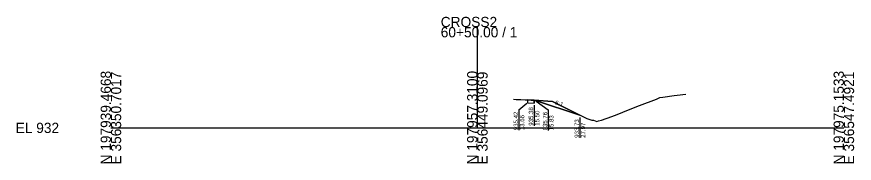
# Model space of a CAD drawing. Extents: x -26 to 203, y -10 to 14021.
# Drawn here: x -25.7 to 202.8, y 1490.3 to 1530.4 of the extents above; entities that cross this region are included whole.
import ezdxf

# ---------------------------------------------------------------- set-up
doc = ezdxf.new("R2010")
doc.units = 0
for name, color, linetype in [('Default', 7, 'Continuous'), ('P_E_XS_Ground', 7, 'Continuous'), ('P_XS', 7, 'Continuous'), ('P_XS_EAR_CommonGrnd', 7, 'Continuous'), ('P_XS_Lane', 7, 'Continuous'), ('P_XS_Rock', 7, 'Continuous')]:
    doc.layers.add(name, color=color, linetype=linetype)

msp = doc.modelspace()

# ---------------------------------------------------------------- linework, layer by layer
at = {"layer": 'Default'}
for p, q in [((100, 1500), (100, 1527.59)), ((0, 1500), (100, 1500)), ((100, 1500), (200, 1500))]:
    msp.add_line(p, q, dxfattribs=at)
at = {"layer": 'P_E_XS_Ground'}
for p, q in [((149.82, 1508.3), (150.61, 1508.37)), ((150.61, 1508.37), (153.73, 1508.85)), ((153.73, 1508.85), (154.52, 1508.94)), ((154.52, 1508.94), (156.89, 1509.2)), ((109.83, 1507.83), (110.55, 1507.8)), ((110.55, 1507.8), (115.5, 1507.6)), ((115.5, 1507.6), (120.5, 1507.2)), ((120.5, 1507.2), (129.85, 1502.53)), ((141.22, 1504.91), (144.22, 1506.13)), ((144.22, 1506.13), (148.91, 1507.86)), ((148.91, 1507.86), (149.82, 1508.3)), ((138.16, 1503.69), (141.22, 1504.91)), ((129.85, 1502.53), (131.24, 1502.11)), ((131.24, 1502.11), (131.69, 1502.12)), ((131.69, 1502.12), (132.62, 1501.78)), ((132.62, 1501.78), (133.06, 1501.93)), ((133.06, 1501.93), (133.85, 1502.13)), ((133.85, 1502.13), (136.69, 1503.12)), ((136.69, 1503.12), (138.16, 1503.69))]:
    msp.add_line(p, q, dxfattribs=at)
at = {"layer": 'P_XS'}
for p, q in [((109.83, 1507.83), (113.83, 1507.67)), ((113.83, 1507.67), (115.5, 1507.54))]:
    msp.add_line(p, q, dxfattribs=at)
at = {"layer": 'P_XS_EAR_CommonGrnd'}
msp.add_lwpolyline([(113.66, 1507.67), (113.66, 1506.84), (115.5, 1506.77), (115.5, 1507.54), (115.83, 1507.51), (127.97, 1503.46), (120.5, 1507.2), (115.5, 1507.6)], close=True, dxfattribs=at)
at = {"layer": 'P_XS_Lane'}
for p, q in [((113.66, 1507.67), (113.66, 1506.84)), ((113.66, 1506.84), (115.5, 1506.77)), ((115.5, 1507.54), (115.5, 1506.77)), ((115.5, 1507.54), (115.83, 1507.51)), ((127.97, 1503.46), (115.83, 1507.51))]:
    msp.add_line(p, q, dxfattribs=at)
at = {"layer": 'P_XS_Rock'}
for p, q in [((111.35, 1504.97), (113.53, 1506.73)), ((115.47, 1506.18), (115.47, 1500.59)), ((116.03, 1507.36), (119.32, 1504.9)), ((111.35, 1504.97), (111.35, 1499.37)), ((119.32, 1504.9), (119.32, 1499.31)), ((127.99, 1502.87), (127.99, 1497.27))]:
    msp.add_line(p, q, dxfattribs=at)

# ---------------------------------------------------------------- texts
at = {"layer": 'Default'}
for s, p in [('CROSS2', (90, 1527.59)), ('60+50.00 / 1', (90, 1524.79)), ('EL 932', (-26, 1498.6))]:
    msp.add_text(s, height=2.8, dxfattribs=at).set_placement(p)
for s, p in [('N 197939.4668', (0, 1490)), ('E 356350.7017', (2.8, 1490)), ('N 197957.3100', (100, 1490)), ('E 356449.0969', (102.8, 1490)), ('N 197975.1533', (200, 1490)), ('E 356547.4921', (202.8, 1490))]:
    msp.add_text(s, height=2.8, rotation=90, dxfattribs=at).set_placement(p)
at = {"layer": 'P_XS_Rock'}
for s, rotation, p in [('6:1', 341.5651, (121.05, 1506.43)), ('935.42', 90, (111.1, 1499.37)), ('935.38', 90, (115.22, 1500.59)), ('15.50', 90, (116.92, 1500.59)), ('935.76', 90, (119.07, 1499.31)), ('13.66', 90, (112.8, 1499.37)), ('15.83', 90, (120.77, 1499.31)), ('933.73', 90, (127.74, 1497.28)), ('27.97', 90, (129.44, 1497.28))]:
    msp.add_text(s, height=1.2, rotation=rotation, dxfattribs=at).set_placement(p)

doc.saveas('drawing.dxf')
